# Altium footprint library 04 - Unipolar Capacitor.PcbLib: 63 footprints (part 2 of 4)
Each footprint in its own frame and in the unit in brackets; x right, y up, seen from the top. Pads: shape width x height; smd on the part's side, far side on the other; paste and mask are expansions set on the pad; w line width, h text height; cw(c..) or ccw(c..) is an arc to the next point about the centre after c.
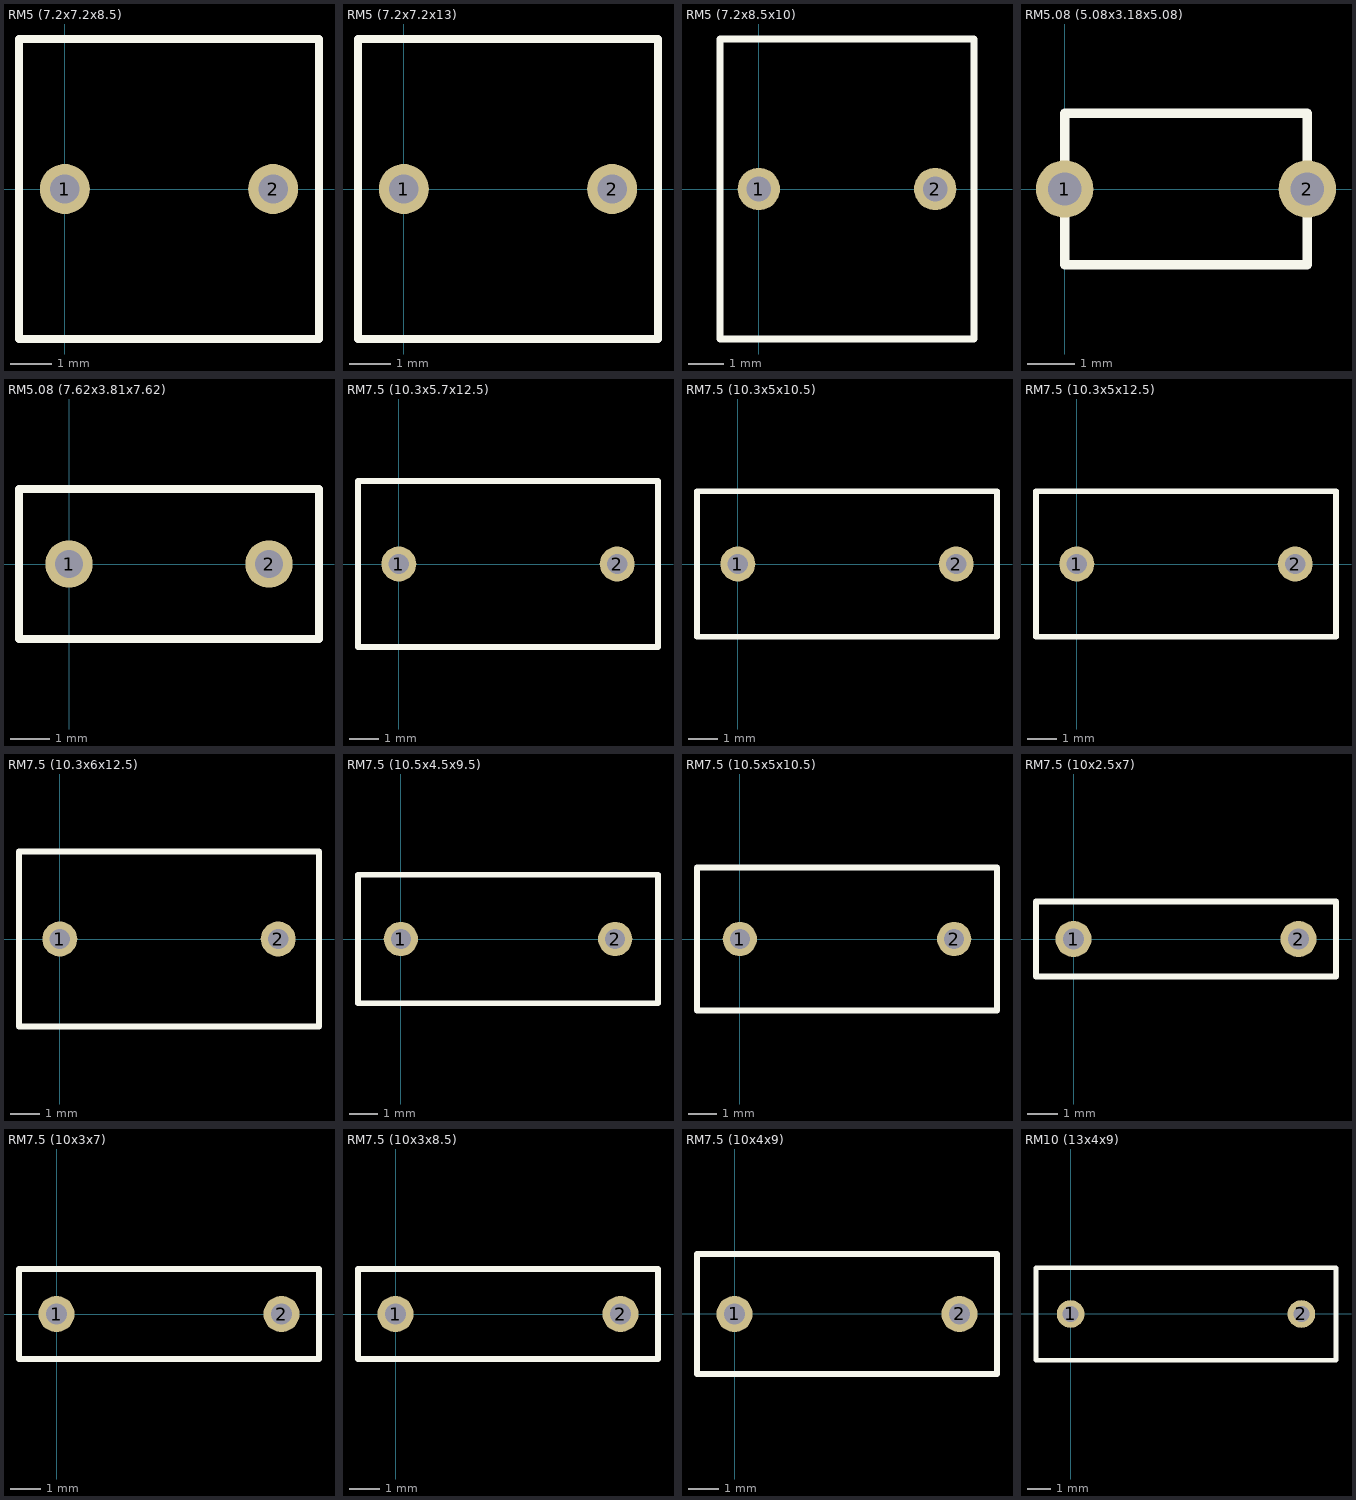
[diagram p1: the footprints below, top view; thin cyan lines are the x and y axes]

## RM5 (7.2x7.2x8.5) [mm] "Radial Thumb Capacitor"
height 8.5
pads (2):
  round 1.2 hole 0.7: 1(0,0) 2(5,0)
Top Overlay:
  lines w0.2: -1.1,-3.6 -1.1,3.6 6.1,3.6 6.1,-3.6 -1.1,-3.6

## RM5 (7.2x7.2x13) [mm] "Radial Thumb Capacitor"
height 13
pads (2):
  round 1.2 hole 0.7: 1(0,0) 2(5,0)
Top Overlay:
  lines w0.2: -1.1,-3.6 6.1,-3.6 6.1,3.6 -1.1,3.6 -1.1,-3.6

## RM5 (7.2x8.5x10) [mm] "Radial Thumb Capacitor"
height 10
pads (2):
  round 1.2 hole 0.7: 1(0,0) 2(5,0)
Top Overlay:
  lines w0.2: -1.1,-4.25 6.1,-4.25 6.1,4.25 -1.1,4.25 -1.1,-4.25

## RM5.08 (5.08x3.18x5.08) [mm] "Radial Thumb Capacitor"
height 5.08
pads (2):
  round 1.2 hole 0.7: 1(0,0) 2(5.08,0)
Top Overlay:
  lines w0.2: 0,-1.59 0,1.59 5.08,1.59 5.08,-1.59 0,-1.59

## RM5.08 (7.62x3.81x7.62) [mm] "Radial Thumb Capacitor"
height 7.62
pads (2):
  round 1.2 hole 0.7: 1(0,0) 2(5.08,0)
Top Overlay:
  lines w0.2: -1.27,-1.905 6.35,-1.905 6.35,1.905 -1.27,1.905 -1.27,-1.905

## RM7.5 (10.3x5.7x12.5) [mm] "Radial Thumb Capacitor"
height 12.5
pads (2):
  round 1.2 hole 0.7: 1(0,0) 2(7.5,0)
Top Overlay:
  lines w0.2: -1.4,-2.85 -1.4,2.85 8.9,2.85 8.9,-2.85 -1.4,-2.85

## RM7.5 (10.3x5x10.5) [mm] "Radial Thumb Capacitor"
height 10.5
pads (2):
  round 1.2 hole 0.7: 1(0,0) 2(7.5,0)
Top Overlay:
  lines w0.2: -1.4,-2.5 8.9,-2.5 8.9,2.5 -1.4,2.5 -1.4,-2.5

## RM7.5 (10.3x5x12.5) [mm] "Radial Thumb Capacitor"
height 12.5
pads (2):
  round 1.2 hole 0.7: 1(0,0) 2(7.5,0)
Top Overlay:
  lines w0.2: -1.4,-2.5 8.9,-2.5 8.9,2.5 -1.4,2.5 -1.4,-2.5

## RM7.5 (10.3x6x12.5) [mm] "Radial Thumb Capacitor"
height 12.5
pads (2):
  round 1.2 hole 0.7: 1(0,0) 2(7.5,0)
Top Overlay:
  lines w0.2: -1.4,-3 8.9,-3 8.9,3 -1.4,3 -1.4,-3

## RM7.5 (10.5x4.5x9.5) [mm] "Radial Thumb Capacitor"
height 9.5
pads (2):
  round 1.2 hole 0.7: 1(0,0) 2(7.5,0)
Top Overlay:
  lines w0.2: -1.5,-2.25 9,-2.25 9,2.25 -1.5,2.25 -1.5,-2.25

## RM7.5 (10.5x5x10.5) [mm] "Radial Thumb Capacitor"
height 10.5
pads (2):
  round 1.2 hole 0.7: 1(0,0) 2(7.5,0)
Top Overlay:
  lines w0.2: -1.5,-2.5 9,-2.5 9,2.5 -1.5,2.5 -1.5,-2.5

## RM7.5 (10x2.5x7) [mm] "Radial Thumb Capacitor"
height 7
pads (2):
  round 1.2 hole 0.7: 1(0,0) 2(7.5,0)
Top Overlay:
  lines w0.2: -1.25,-1.25 8.75,-1.25 8.75,1.25 -1.25,1.25 -1.25,-1.25

## RM7.5 (10x3x7) [mm] "Radial Thumb Capacitor"
height 7
pads (2):
  round 1.2 hole 0.7: 1(0,0) 2(7.5,0)
Top Overlay:
  lines w0.2: -1.25,-1.5 8.75,-1.5 8.75,1.5 -1.25,1.5 -1.25,-1.5

## RM7.5 (10x3x8.5) [mm] "Radial Thumb Capacitor"
height 8.5
pads (2):
  round 1.2 hole 0.7: 1(0,0) 2(7.5,0)
Top Overlay:
  lines w0.2: -1.25,-1.5 -1.25,1.5 8.75,1.5 8.75,-1.5 -1.25,-1.5

## RM7.5 (10x4x9) [mm] "Radial Thumb Capacitor"
height 9
pads (2):
  round 1.2 hole 0.7: 1(0,0) 2(7.5,0)
Top Overlay:
  lines w0.2: -1.25,-2 -1.25,2 8.75,2 8.75,-2 -1.25,-2

## RM10 (13x4x9) [mm] "Radial Thumb Capacitor"
height 9
pads (2):
  round 1.2 hole 0.7: 1(0,0) 2(10,0)
Top Overlay:
  lines w0.2: -1.5,-2 11.5,-2 11.5,2 -1.5,2 -1.5,-2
